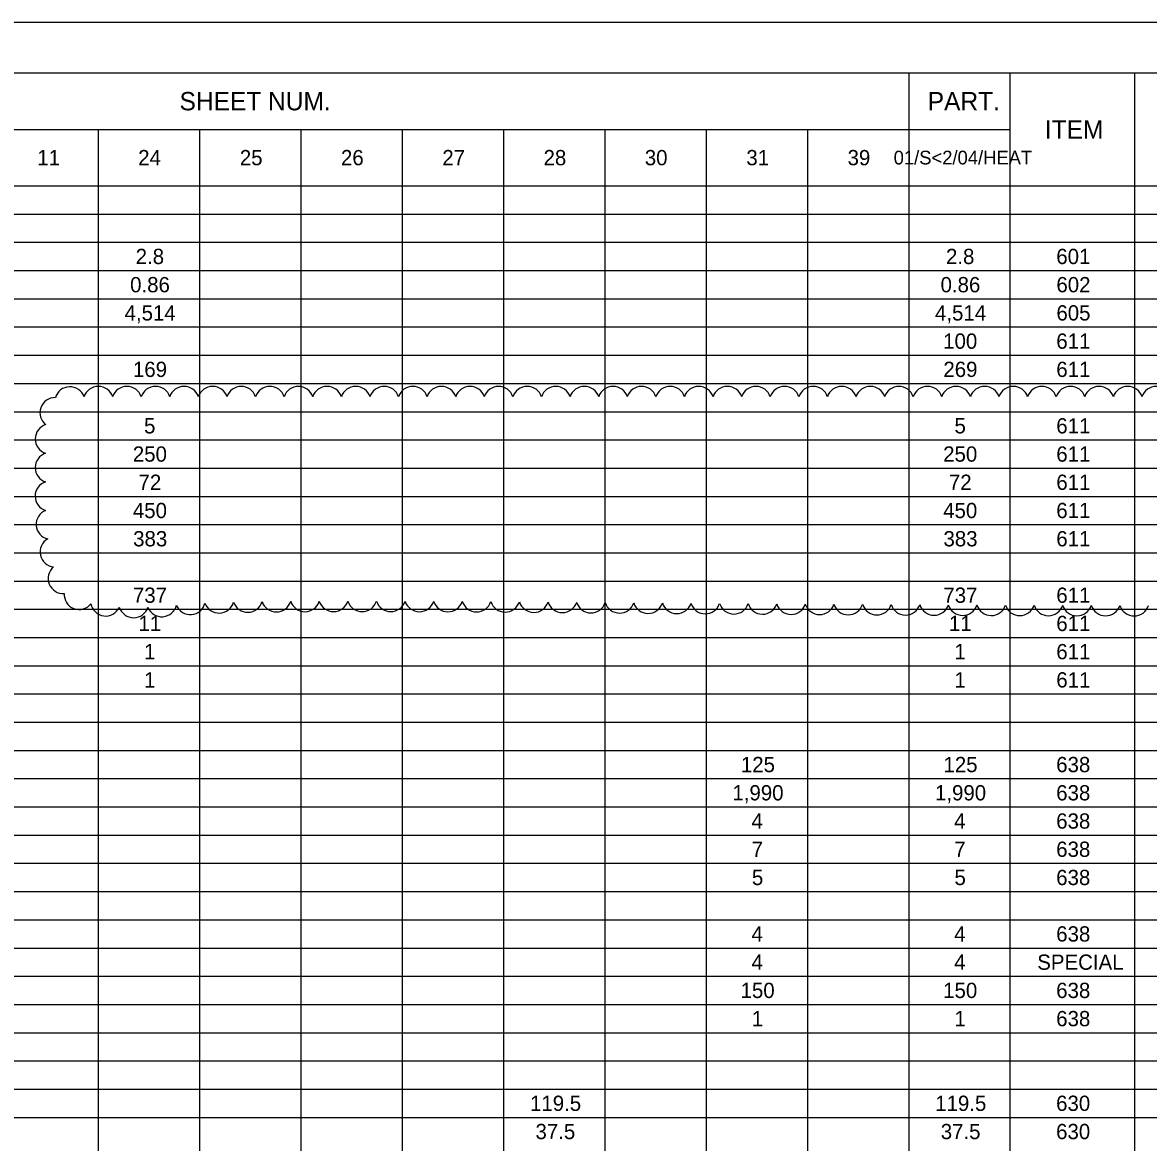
# Model space of a CAD drawing. Extents: x 0 to 36.7, y 0 to 22.
# Drawn here: x 5.77 to 16.94, y 10.89 to 22 of the extents above; entities that cross this region are included whole.
import ezdxf

# ---------------------------------------------------------------- set-up
doc = ezdxf.new("R2010")
doc.units = 0
for name, color, linetype in [('SC_Scratch1', 7, 'Continuous'), ('SH_Border', 7, 'Continuous'), ('SH_Cut_Line', 7, 'Continuous'), ('SH_Text', 7, 'Continuous')]:
    doc.layers.add(name, color=color, linetype=linetype)

msp = doc.modelspace()

# ---------------------------------------------------------------- linework, layer by layer
at = {"layer": 'SC_Scratch1'}
for centre, start, end in [((6.241, 18.238), 19.2217, 164.2217), ((6.524, 18.242), 17.5, 162.5), ((6.807, 18.242), 17.5, 162.5), ((7.091, 18.242), 17.5, 162.5), ((7.374, 18.242), 17.5, 162.5), ((7.658, 18.242), 17.5, 162.5), ((7.941, 18.242), 17.5, 162.5), ((8.225, 18.242), 17.5, 162.5), ((8.508, 18.242), 17.5, 162.5), ((8.792, 18.242), 17.5, 162.5), ((9.076, 18.242), 17.5, 162.5), ((9.359, 18.242), 17.5, 162.5), ((9.643, 18.242), 17.5, 162.5), ((9.926, 18.242), 17.5, 162.5), ((10.21, 18.242), 17.5, 162.5), ((10.493, 18.242), 17.5, 162.5), ((10.777, 18.242), 17.5, 162.5), ((11.06, 18.242), 17.5, 162.5), ((11.344, 18.242), 17.5, 162.5), ((11.628, 18.242), 17.5, 162.5), ((11.911, 18.242), 17.5, 162.5), ((12.195, 18.242), 17.5, 162.5), ((12.478, 18.242), 17.5, 162.5), ((12.762, 18.242), 17.5, 162.5), ((13.045, 18.242), 17.5, 162.5), ((13.329, 18.242), 17.5, 162.5), ((13.613, 18.242), 17.5, 162.5), ((13.896, 18.242), 17.5, 162.5), ((14.18, 18.242), 17.5, 162.5), ((14.463, 18.242), 17.5, 162.5), ((14.747, 18.242), 17.5, 162.5), ((15.03, 18.242), 17.5, 162.5), ((15.314, 18.242), 17.5, 162.5), ((15.597, 18.242), 17.5, 162.5), ((15.881, 18.242), 17.5, 162.5), ((16.165, 18.242), 17.5, 162.5), ((16.448, 18.242), 17.5, 162.5), ((16.732, 18.242), 17.5, 162.5), ((17.015, 18.242), 17.5, 162.5), ((6.093, 18.13), 88.0862, 233.0862), ((6.047, 17.869), 107.0339, 252.0339), ((6.046, 17.585), 107.5, 252.5), ((6.046, 17.302), 107.5362, 252.5362), ((6.056, 17.022), 111.5223, 256.5223), ((6.095, 16.748), 119.4236, 264.4236), ((6.175, 16.485), 129.3504, 274.3504), ((6.334, 16.327), 176.3526, 321.3526), ((6.596, 16.262), 190.6371, 335.6371), ((6.874, 16.245), 197.5377, 342.5377), ((7.154, 16.255), 201.6347, 346.6347), ((7.436, 16.276), 201.7957, 346.7957), ((7.721, 16.291), 199.3232, 344.3232), ((8.005, 16.299), 198.5232, 343.5232), ((8.289, 16.303), 198.1047, 343.1047), ((8.573, 16.305), 197.8361, 342.8361), ((8.857, 16.306), 197.6448, 342.6448), ((9.14, 16.306), 197.4996, 342.4996), ((9.424, 16.306), 197.3845, 342.3845), ((9.708, 16.305), 197.2904, 342.2904), ((9.991, 16.304), 197.2116, 342.2116), ((10.275, 16.303), 197.1443, 342.1443), ((10.558, 16.301), 197.0859, 342.0859), ((10.842, 16.298), 197.0347, 342.0347), ((11.126, 16.296), 196.9894, 341.9894), ((11.409, 16.293), 196.9611, 341.9611), ((11.693, 16.291), 196.9822, 341.9822), ((11.976, 16.288), 197.0074, 342.0074), ((12.26, 16.286), 197.0322, 342.0322), ((12.543, 16.284), 197.0564, 342.0564), ((12.827, 16.282), 197.0802, 342.0802), ((13.11, 16.28), 197.1034, 342.1034), ((13.394, 16.278), 197.1263, 342.1263), ((13.677, 16.276), 197.1486, 342.1486), ((13.961, 16.274), 197.1706, 342.1706), ((14.245, 16.273), 197.1921, 342.1921), ((14.528, 16.271), 197.2132, 342.2132), ((14.812, 16.27), 197.234, 342.234), ((15.095, 16.268), 197.2543, 342.2543), ((15.379, 16.267), 197.2743, 342.2743), ((15.662, 16.266), 197.294, 342.294), ((15.946, 16.265), 197.3133, 342.3133), ((16.229, 16.264), 197.3322, 342.3322), ((16.513, 16.264), 197.3508, 342.3508), ((16.796, 16.263), 197.3692, 342.3692)]:
    msp.add_arc(centre, 0.149, start, end, dxfattribs=at)
at = {"layer": 'SH_Border'}
msp.add_lwpolyline([(1.5, 21.5), (33.5, 21.5), (33.5, 0.5), (1.5, 0.5)], close=True, dxfattribs=at)
at = {"layer": 'SH_Cut_Line'}
msp.add_lwpolyline([(0, 0), (34, 0), (34, 22), (0, 22)], close=True, dxfattribs=at)
at = {"layer": 'SH_Text'}
for p, q in [((1.5, 21.5), (32, 21.5)), ((14.56, 21.5), (14.56, 0.5)), ((15.564, 21.5), (15.564, 0.5)), ((16.799, 21.5), (16.799, 0.5)), ((1.5, 20.94), (15.564, 20.94)), ((6.523, 20.94), (6.523, 0.5)), ((7.528, 20.94), (7.528, 0.5)), ((8.532, 20.94), (8.532, 0.5)), ((9.537, 20.94), (9.537, 0.5)), ((10.541, 20.94), (10.541, 0.5)), ((11.546, 20.94), (11.546, 0.5)), ((12.55, 20.94), (12.55, 0.5)), ((13.555, 20.94), (13.555, 0.5)), ((1.5, 20.38), (32, 20.38)), ((1.5, 20.1), (32, 20.1)), ((1.5, 19.82), (32, 19.82)), ((1.5, 19.54), (32, 19.54)), ((1.5, 19.26), (32, 19.26)), ((1.5, 18.98), (32, 18.98)), ((1.5, 18.7), (32, 18.7)), ((1.5, 18.42), (32, 18.42)), ((1.5, 18.14), (32, 18.14)), ((1.5, 17.86), (32, 17.86)), ((1.5, 17.58), (32, 17.58)), ((1.5, 17.3), (32, 17.3)), ((1.5, 17.02), (32, 17.02)), ((1.5, 16.74), (32, 16.74)), ((1.5, 16.46), (32, 16.46)), ((1.5, 16.18), (32, 16.18)), ((1.5, 15.9), (32, 15.9)), ((1.5, 15.62), (32, 15.62)), ((1.5, 15.34), (32, 15.34)), ((1.5, 15.06), (32, 15.06)), ((1.5, 14.78), (32, 14.78)), ((1.5, 14.5), (32, 14.5)), ((1.5, 14.22), (32, 14.22)), ((1.5, 13.94), (32, 13.94)), ((1.5, 13.66), (32, 13.66)), ((1.5, 13.38), (32, 13.38)), ((1.5, 13.1), (32, 13.1)), ((1.5, 12.82), (32, 12.82)), ((1.5, 12.54), (32, 12.54)), ((1.5, 12.26), (32, 12.26)), ((1.5, 11.98), (32, 11.98)), ((1.5, 11.7), (32, 11.7)), ((1.5, 11.42), (32, 11.42)), ((1.5, 11.14), (32, 11.14))]:
    msp.add_line(p, q, dxfattribs=at)

# ---------------------------------------------------------------- texts
for s, height, p in [('SHEET NUM.', 0.1818, (7.329, 21.129)), ('PART.', 0.1818, (14.749, 21.129)), ('ITEM', 0.1818, (15.91, 20.849)), ('11', 0.1515, (5.918, 20.584)), ('24', 0.1515, (6.919, 20.584)), ('25', 0.1515, (7.927, 20.584)), ('26', 0.1515, (8.93, 20.584)), ('27', 0.1515, (9.935, 20.584)), ('28', 0.1515, (10.939, 20.584)), ('30', 0.1515, (11.943, 20.584)), ('31', 0.1515, (12.95, 20.584)), ('39', 0.1515, (13.954, 20.584)), ('01/S<2/04/HEAT', 0.13638, (14.411, 20.592)), ('2.8', 0.1515, (6.894, 19.604)), ('2.8', 0.1515, (14.93, 19.604)), ('601', 0.1515, (16.024, 19.604)), ('0.86', 0.1515, (6.839, 19.324)), ('0.86', 0.1515, (14.876, 19.324)), ('602', 0.1515, (16.025, 19.324)), ('4,514', 0.1515, (6.784, 19.044)), ('4,514', 0.1515, (14.821, 19.044)), ('605', 0.1515, (16.025, 19.044)), ('100', 0.1515, (14.902, 18.764)), ('611', 0.1515, (16.024, 18.764)), ('169', 0.1515, (6.867, 18.484)), ('269', 0.1515, (14.904, 18.484)), ('611', 0.1515, (16.024, 18.484)), ('5', 0.152, (6.977, 17.924)), ('5', 0.152, (15.014, 17.924)), ('611', 0.1515, (16.024, 17.924)), ('250', 0.1515, (6.866, 17.644)), ('250', 0.1515, (14.902, 17.644)), ('611', 0.1515, (16.024, 17.644)), ('72', 0.1515, (6.922, 17.364)), ('72', 0.1515, (14.959, 17.364)), ('611', 0.1515, (16.024, 17.364)), ('450', 0.1515, (6.866, 17.084)), ('450', 0.1515, (14.902, 17.084)), ('611', 0.1515, (16.024, 17.084)), ('383', 0.1515, (6.869, 16.804)), ('383', 0.1515, (14.905, 16.804)), ('611', 0.1515, (16.024, 16.804)), ('737', 0.1515, (6.867, 16.244)), ('737', 0.1515, (14.904, 16.244)), ('611', 0.1515, (16.024, 16.244)), ('11', 0.1515, (6.922, 15.964)), ('11', 0.1515, (14.959, 15.964)), ('611', 0.1515, (16.024, 15.964)), ('1', 0.152, (6.977, 15.684)), ('1', 0.152, (15.013, 15.684)), ('611', 0.1515, (16.024, 15.684)), ('1', 0.152, (6.977, 15.404)), ('1', 0.152, (15.013, 15.404)), ('611', 0.1515, (16.024, 15.404)), ('125', 0.1515, (12.896, 14.564)), ('125', 0.1515, (14.905, 14.564)), ('638', 0.1515, (16.023, 14.564)), ('1,990', 0.1515, (12.812, 14.284)), ('1,990', 0.1515, (14.821, 14.284)), ('638', 0.1515, (16.023, 14.284)), ('4', 0.152, (13.001, 14.004)), ('4', 0.152, (15.011, 14.004)), ('638', 0.1515, (16.023, 14.004)), ('7', 0.152, (13.003, 13.724)), ('7', 0.152, (15.012, 13.724)), ('638', 0.1515, (16.023, 13.724)), ('5', 0.152, (13.005, 13.444)), ('5', 0.152, (15.014, 13.444)), ('638', 0.1515, (16.023, 13.444)), ('4', 0.152, (13.001, 12.884)), ('4', 0.152, (15.011, 12.884)), ('638', 0.1515, (16.023, 12.884)), ('4', 0.152, (13.001, 12.604)), ('4', 0.152, (15.011, 12.604)), ('SPECIAL', 0.1515, (15.835, 12.604)), ('150', 0.1515, (12.893, 12.324)), ('150', 0.1515, (14.902, 12.324)), ('638', 0.1515, (16.023, 12.324)), ('1', 0.152, (13.004, 12.044)), ('1', 0.152, (15.013, 12.044)), ('638', 0.1515, (16.023, 12.044)), ('119.5', 0.1515, (10.805, 11.204)), ('119.5', 0.1515, (14.823, 11.204)), ('630', 0.1515, (16.022, 11.204)), ('37.5', 0.1515, (10.859, 10.924)), ('37.5', 0.1515, (14.878, 10.924)), ('630', 0.1515, (16.022, 10.924))]:
    msp.add_text(s, height=height, dxfattribs=at).set_placement(p)

doc.saveas('drawing.dxf')
